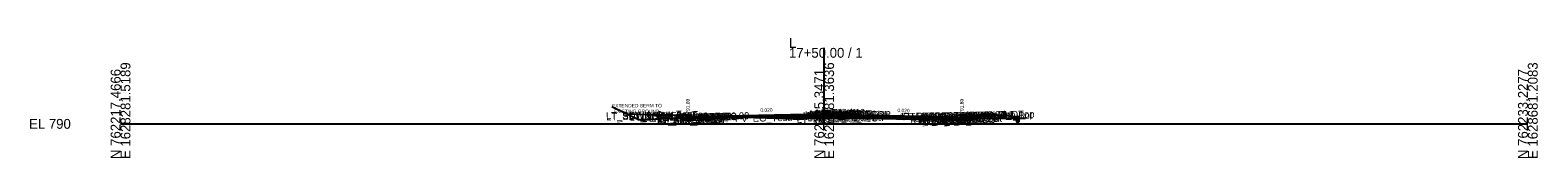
# Model space of a CAD drawing. Extents: x -26 to 4403, y -510 to 9556.
# Drawn here: x -25.7 to 402.8, y 7490.3 to 7524.4 of the extents above; entities that cross this region are included whole.
import ezdxf

# ---------------------------------------------------------------- set-up
doc = ezdxf.new("R2010")
doc.units = 0
for name, color, linetype in [('Default', 7, 'Continuous'), ('Exist CMT Pavement', 7, 'Continuous'), ('Exist Cross Section Cell', 7, 'Continuous'), ('Exist XS Ground Line', 7, 'Continuous'), ('Exist XS Void Line', 7, 'Continuous'), ('Prop CMT Conc Surface', 7, 'Continuous'), ('Prop CMT Concrete Structures', 7, 'Continuous'), ('Prop CMT Pvmt Course 1', 7, 'Continuous'), ('Prop CMT Pvmt Course 1 CG', 7, 'Continuous'), ('Prop CMT Pvmt Course 1 Wedge', 7, 'Continuous'), ('Prop CMT Pvmt Course 2', 7, 'Continuous'), ('Prop CMT Pvmt Course 2 Wedge', 7, 'Continuous'), ('Prop CMT Pvmt Course 3', 7, 'Continuous'), ('Prop CMT Pvmt Course 3 Wedge', 7, 'Continuous'), ('Prop CMT Pvmt Surface', 7, 'Continuous'), ('Prop CMT Pvmt Wedge Surface 1', 7, 'Continuous'), ('Prop CMT Pvmt Wedge Surface 2', 7, 'Continuous'), ('Prop CMT Pvmt Wedge Surface 3', 7, 'Continuous'), ('Prop CMT Slope Grass', 7, 'Continuous'), ('Prop CMT Subgrade Earthwork', 7, 'Continuous'), ('Prop XS Finish Grade CurbGutter', 7, 'Continuous'), ('Prop XS Hydro Elevations', 7, 'Continuous'), ('Prop XS SE Text', 7, 'Continuous'), ('Prop XS Side Slope Text', 7, 'Continuous'), ('Scratch_Level_0', 7, 'Continuous')]:
    doc.layers.add(name, color=color, linetype=linetype)

msp = doc.modelspace()

# ---------------------------------------------------------------- linework, layer by layer
at = {"layer": 'Exist CMT Pavement'}
for points in [[(163.26, 7501.84), (170.58, 7501.94), (180.37, 7501.79), (180.75, 7501.78), (181.13, 7501.77), (191.19, 7501.47)], [(191.19, 7501.47), (191.34, 7501.46)]]:
    msp.add_lwpolyline(points, dxfattribs=at)
at = {"layer": 'Exist Cross Section Cell'}
for p, q in [((200, 7500), (200, 7521.59)), ((0, 7500), (200, 7500)), ((200, 7500), (400, 7500))]:
    msp.add_line(p, q, dxfattribs=at)
at = {"layer": 'Exist XS Ground Line'}
for p, q in [((139.65, 7504.97), (147.23, 7501.25)), ((147.23, 7501.25), (149.96, 7501.25))]:
    msp.add_line(p, q, dxfattribs=at)
msp.add_lwpolyline([(149.96, 7501.25), (150.33, 7501.27), (160.36, 7501.79), (170.58, 7501.94), (180.37, 7501.79), (180.75, 7501.78), (181.13, 7501.77), (191.19, 7501.47), (193.08, 7501.34), (196.33, 7501.62)], dxfattribs=at)
at = {"layer": 'Exist XS Void Line'}
msp.add_line((196.33, 7501.62), (257.17, 7501.62), dxfattribs=at)
at = {"layer": 'Prop CMT Conc Surface'}
for points in [[(156.75, 7502.48), (151.75, 7502.58)], [(161.25, 7501.9), (161.25, 7502.4), (160.75, 7502.4)], [(163.25, 7502.02), (161.25, 7501.9)], [(237.1, 7502.01), (239.1, 7501.89)], [(239.1, 7501.89), (239.1, 7502.39), (239.6, 7502.39)], [(243.61, 7502.48), (248.61, 7502.58)]]:
    msp.add_lwpolyline(points, dxfattribs=at)
at = {"layer": 'Prop CMT Concrete Structures'}
for points in [[(151.75, 7502.25), (151.75, 7502.58)], [(151.75, 7502.58), (156.75, 7502.48)], [(156.75, 7502.15), (151.75, 7502.25)], [(156.75, 7502.48), (156.75, 7502.15)], [(163.25, 7502.02), (161.25, 7501.9), (161.25, 7502.4), (160.75, 7502.4)], [(160.75, 7502.4), (160.75, 7501.38), (163.25, 7501.43)], [(163.25, 7501.43), (163.25, 7502.02)], [(208, 7502.59), (207.99, 7502.76), (207.24, 7503.01), (206, 7503.27), (204.76, 7503.25), (204.01, 7503), (204, 7502.83)], [(204, 7502.83), (208, 7502.59)], [(237.1, 7502.01), (239.1, 7501.89), (239.1, 7502.39), (239.6, 7502.39)], [(239.6, 7502.39), (239.6, 7501.38), (237.1, 7501.42)], [(237.1, 7501.42), (237.1, 7502.01)], [(248.61, 7502.58), (243.61, 7502.48)], [(243.61, 7502.48), (243.61, 7502.14)], [(243.61, 7502.14), (248.61, 7502.24)], [(248.61, 7502.24), (248.61, 7502.58)]]:
    msp.add_lwpolyline(points, dxfattribs=at)
at = {"layer": 'Prop CMT Pvmt Course 1'}
for points in [[(204, 7502.83), (163.25, 7502.02)], [(163.25, 7501.89), (204, 7502.7)], [(163.25, 7502.02), (163.25, 7501.77), (163.25, 7501.77), (163.25, 7501.89)], [(204, 7502.83), (208, 7502.59)], [(204, 7502.58), (204, 7502.83)], [(204, 7502.58), (204, 7502.83)], [(204, 7502.7), (204, 7502.58), (204, 7502.58)], [(208, 7502.34), (204, 7502.58)], [(208, 7502.59), (208, 7502.34)], [(208, 7502.59), (237.1, 7502.01)], [(208, 7502.34), (208, 7502.59)], [(237.1, 7501.76), (208, 7502.34)], [(237.1, 7502.01), (237.1, 7501.76)]]:
    msp.add_lwpolyline(points, dxfattribs=at)
msp.add_lwpolyline([(208, 7502.34), (208, 7502.47), (208, 7502.47), (208, 7502.34)], close=True, dxfattribs=at)
at = {"layer": 'Prop CMT Pvmt Course 1 CG'}
for points in [[(163.25, 7501.43), (160.25, 7501.37), (159.91, 7501.03)], [(159.91, 7501.03), (163.25, 7501.1)], [(237.1, 7501.42), (240.1, 7501.37), (240.44, 7501.03)], [(237.1, 7501.09), (237.1, 7501.42)], [(240.44, 7501.03), (237.1, 7501.09)]]:
    msp.add_lwpolyline(points, dxfattribs=at)
at = {"layer": 'Prop CMT Pvmt Course 1 Wedge'}
for points in [[(163.25, 7501.89), (170.58, 7502.04), (180.37, 7502.23), (180.75, 7502.24), (181.13, 7502.25), (191.19, 7502.45), (193.05, 7502.49), (193.08, 7502.49), (193.09, 7502.49), (193.1, 7502.49), (193.14, 7502.49), (196.33, 7502.55), (204, 7502.7)], [(204, 7502.58), (196.33, 7502.43), (193.14, 7502.36), (193.1, 7502.36), (193.09, 7502.36), (193.08, 7502.36), (193.05, 7502.36), (191.19, 7502.32), (181.13, 7502.12), (180.75, 7502.11), (180.37, 7502.11), (171.32, 7501.93), (170.58, 7501.94), (163.25, 7501.83)], [(163.25, 7501.83), (163.25, 7501.89)], [(204, 7502.7), (204, 7502.58)]]:
    msp.add_lwpolyline(points, dxfattribs=at)
at = {"layer": 'Prop CMT Pvmt Course 2'}
for points in [[(163.25, 7501.43), (163.25, 7501.43), (163.25, 7501.77), (163.25, 7501.77)], [(163.25, 7501.77), (163.25, 7501.43)], [(204, 7502.58), (208, 7502.34)], [(204, 7502.25), (204, 7502.58)], [(208, 7502.01), (204, 7502.25)], [(208, 7502.34), (208, 7502.01)], [(208, 7502.01), (208, 7502.34)], [(208, 7502.34), (237.1, 7501.76)], [(237.1, 7501.42), (208, 7502.01)], [(237.1, 7501.76), (237.1, 7501.42)]]:
    msp.add_lwpolyline(points, dxfattribs=at)
at = {"layer": 'Prop CMT Pvmt Course 2 Wedge'}
for points in [[(204, 7502.25), (196.33, 7502.09), (193.14, 7502.03), (193.1, 7502.03), (193.09, 7502.03), (193.08, 7502.03), (193.05, 7502.03), (191.19, 7501.99), (181.13, 7501.79), (180.75, 7501.78), (180.7, 7501.78), (180.37, 7501.79), (171.32, 7501.93)], [(171.32, 7501.93), (180.37, 7502.11)], [(180.37, 7502.11), (180.75, 7502.11), (181.13, 7502.12), (191.19, 7502.32), (193.05, 7502.36), (193.08, 7502.36), (193.09, 7502.36), (193.1, 7502.36), (193.14, 7502.36), (196.33, 7502.43), (204, 7502.58)], [(204, 7502.58), (204, 7502.25)]]:
    msp.add_lwpolyline(points, dxfattribs=at)
at = {"layer": 'Prop CMT Pvmt Course 3'}
for points in [[(163.25, 7501.43), (163.25, 7501.43), (163.25, 7501.1), (163.25, 7501.1)], [(163.25, 7501.1), (163.25, 7501.43)], [(204, 7502.25), (208, 7502.01)], [(204, 7501.91), (204, 7502.25)], [(208, 7501.67), (204, 7501.91)], [(208, 7502.01), (208, 7501.67)], [(208, 7502.01), (237.1, 7501.42)], [(208, 7501.67), (208, 7502.01)], [(237.1, 7501.09), (208, 7501.67)], [(237.1, 7501.42), (237.1, 7501.09)]]:
    msp.add_lwpolyline(points, dxfattribs=at)
at = {"layer": 'Prop CMT Pvmt Course 3 Wedge'}
for points in [[(204, 7501.71), (196.33, 7501.62), (193.14, 7501.34), (193.1, 7501.34), (193.09, 7501.34), (193.08, 7501.34), (193.05, 7501.34), (191.19, 7501.47), (181.13, 7501.77), (180.75, 7501.78), (180.69, 7501.78)], [(180.69, 7501.78), (180.75, 7501.78)], [(180.75, 7501.78), (181.13, 7501.79), (191.19, 7501.99), (193.05, 7502.03), (193.08, 7502.03), (193.09, 7502.03), (193.1, 7502.03), (193.14, 7502.03), (196.33, 7502.09), (204, 7502.25)], [(204, 7502.25), (204, 7501.71)]]:
    msp.add_lwpolyline(points, dxfattribs=at)
at = {"layer": 'Prop CMT Pvmt Surface'}
for points in [[(204, 7502.83), (163.25, 7502.02)], [(204, 7502.83), (208, 7502.59)], [(208, 7502.59), (237.1, 7502.01)]]:
    msp.add_lwpolyline(points, dxfattribs=at)
at = {"layer": 'Prop CMT Pvmt Wedge Surface 1'}
for points in [[(204, 7502.7), (163.25, 7501.89)], [(163.25, 7501.77), (163.25, 7502.02)], [(163.25, 7501.89), (163.25, 7501.77), (163.25, 7501.77)], [(204, 7502.83), (204, 7502.58), (204, 7502.58), (204, 7502.7)]]:
    msp.add_lwpolyline(points, dxfattribs=at)
at = {"layer": 'Prop CMT Pvmt Wedge Surface 2'}
for points in [[(204, 7502.58), (163.25, 7501.77)], [(163.25, 7501.77), (163.25, 7502.02)], [(204, 7502.83), (204, 7502.58)]]:
    msp.add_lwpolyline(points, dxfattribs=at)
at = {"layer": 'Prop CMT Pvmt Wedge Surface 3'}
for points in [[(204, 7502.25), (163.25, 7501.43)], [(163.25, 7501.43), (163.25, 7502.02)], [(204, 7502.83), (204, 7502.25)]]:
    msp.add_lwpolyline(points, dxfattribs=at)
at = {"layer": 'Prop CMT Slope Grass'}
for p, q in [((248.61, 7502.57), (249.1, 7502.58)), ((249.1, 7502.58), (254.68, 7502.12))]:
    msp.add_line(p, q, dxfattribs=at)
for points in [[(151.25, 7502.58), (144.21, 7502.73)], [(160.75, 7502.4), (151.25, 7502.58)], [(239.6, 7502.39), (248.61, 7502.57)], [(254.68, 7502.12), (254.68, 7500.62), (255.35, 7500.62), (255.35, 7501.62)]]:
    msp.add_lwpolyline(points, dxfattribs=at)
at = {"layer": 'Prop CMT Subgrade Earthwork'}
msp.add_line((191.34, 7501.46), (191.34, 7501.66), dxfattribs=at)
for points in [[(163.25, 7501.1), (159.91, 7501.03), (158.5, 7502.44)], [(163.25, 7501.1), (163.26, 7501.83)], [(163.25, 7501.1), (163.25, 7501.1)], [(204, 7501.91), (191.34, 7501.66)], [(204, 7501.91), (208, 7501.67)], [(208, 7501.67), (237.1, 7501.09)], [(237.1, 7501.09), (240.44, 7501.03), (241.84, 7502.43)]]:
    msp.add_lwpolyline(points, dxfattribs=at)
at = {"layer": 'Prop XS Finish Grade CurbGutter'}
for p, q in [((254.68, 7502.12), (254.87, 7502.12)), ((254.68, 7502.12), (255.35, 7502.12)), ((254.68, 7502.12), (254.68, 7501.12)), ((254.68, 7501.12), (254.68, 7500.62)), ((254.68, 7501.12), (255.35, 7501.12)), ((254.68, 7500.62), (255.35, 7500.62)), ((255.35, 7501.7), (254.99, 7502.07)), ((255.35, 7501.7), (255.35, 7501.12)), ((255.35, 7501.62), (255.35, 7501.62)), ((255.35, 7501.12), (255.35, 7500.62))]:
    msp.add_line(p, q, dxfattribs=at)
msp.add_arc((254.87, 7501.95), 0.166, 43.9997, 90, dxfattribs=at)

# ---------------------------------------------------------------- texts
at = {"layer": 'Default'}
msp.add_text('-', height=0.0001, dxfattribs=at).set_placement((0, 7500))
at = {"layer": 'Exist Cross Section Cell'}
for s, p in [('17+50.00 / 1', (190, 7518.79)), ('L', (190, 7521.59)), ('EL 790', (-26, 7498.6))]:
    msp.add_text(s, height=2.8, dxfattribs=at).set_placement(p)
for s, p in [('E 1628281.5189', (2.8, 7490)), ('E 1628481.3636', (202.8, 7490)), ('E 1628681.2083', (402.8, 7490)), ('N 762217.4666', (0, 7490)), ('N 762225.3471', (200, 7490)), ('N 762233.2277', (400, 7490))]:
    msp.add_text(s, height=2.8, rotation=90, dxfattribs=at).set_placement(p)
at = {"layer": 'Prop XS Hydro Elevations'}
for p in [(161.75, 7502.9), (239.6, 7502.89)]:
    msp.add_text('791.89', height=1, rotation=90, dxfattribs=at).set_placement(p)
at = {"layer": 'Prop XS SE Text'}
for rotation, p in [(1.1458, (181.86, 7503.39)), (358.8541, (220.82, 7503.33))]:
    msp.add_text('0.020', height=1, rotation=rotation, dxfattribs=at).set_placement(p)
at = {"layer": 'Prop XS Side Slope Text'}
for s, p in [('EXTENDED BERM TO', (139.68, 7504.69)), ('EXISTING GROUND', (140.19, 7503.06))]:
    msp.add_text(s, height=1, dxfattribs=at).set_placement(p)
msp.add_text('VAR.', height=1, rotation=355.293, dxfattribs=at).set_placement((250.28, 7502.57))
at = {"layer": 'Scratch_Level_0'}
for s, p in [('LT_SDWK_Out_Top', (138.01, 7501.31)), ('LT_SDWK_In_Top', (144.63, 7501.24)), ('LT_PV2_IEEOP', (193.97, 7501.38)), ('LT_PV1_IEEOP', (194.54, 7501.52)), ('LT_PV2_PGL1', (194.9, 7501.4)), ('LT_PV2_PGL', (195.23, 7501.4)), ('LT_PV1_PGL', (195.8, 7501.67)), ('MI_Face In', (195.92, 7501.83)), ('MI_Top In', (197.63, 7502.1)), ('RT_PV1_OEEOP', (197.85, 7501.26)), ('17+50.00', (197.84, 7501.82)), ('17+50.00', (198.07, 7501.95)), ('MI_Face Out', (198.28, 7501.56)), ('MI_Top Out', (198.49, 7501.83)), ('RT_PV1_IEEOP', (198.49, 7501.27)), ('MI_Crown', (199.09, 7502.13)), ('MI_Bot Out', (199.28, 7501.42)), ('RT_PV1_PGL', (199.75, 7501.42)), ('17+50.00', (200.47, 7502.01)), ('17+50.00', (201.75, 7501.66)), ('17+50.00', (201.82, 7501.61)), ('RT_Sub_Trench_Out_DLT', (222.39, 7501.04)), ('RT_CG_Top_BOC', (227.86, 7501.15)), ('RT_SDWK_In_Top', (231.44, 7501.23)), ('RT_SDWK_Out_Top', (234.82, 7501.3)), ('RT_Shld_O', (241.17, 7501.42)), ('LT_SDWK_Out_Bot', (138.04, 7500.98)), ('LT_SDWK_In_Bot', (144.66, 7500.91)), ('LT_PV_Sub_Tie_Out', (148.23, 7500.53)), ('LT_PV_OEEOP_EG', (150.82, 7500.59)), ('17+50.00', (152.1, 7501.25)), ('LT_Sub_OEEOP', (152.48, 7499.88)), ('LT_PV2_OEEOP', (152.58, 7500.55)), ('LT_PV3_OEEOP', (152.58, 7500.22)), ('LT_PV1_OEEOP', (153.15, 7500.69)), ('LT_Sub_OEOT', (153.35, 7499.9)), ('LT_PV2_OEOT', (153.45, 7500.57)), ('LT_PV3_OEOT', (153.45, 7500.24)), ('LT_PV1_OEOT', (154.01, 7500.83)), ('17+50.00', (167.51, 7501.1)), ('LT_PV_EG_TestPt', (170.06, 7500.42)), ('LT_PV_IEEOP_EG', (192.21, 7500.24)), ('LT_PV3_IEEOP', (193.97, 7501.05)), ('LT_PV3_PGL1', (194.9, 7501.06)), ('LT_PV3_PGL', (195.23, 7501.07)), ('LT_PV4_PGL', (195.23, 7500.74)), ('RT_Sub_OEEOP', (197.19, 7500.46)), ('RT_PV2_OEEOP', (197.28, 7501.13)), ('RT_PV3_OEEOP', (197.28, 7500.79)), ('RT_PV2_IEEOP', (197.93, 7501.14)), ('RT_PV2_PGL1', (198.86, 7501.16)), ('RT_PV3_PGL1', (198.86, 7500.82)), ('RT_PV2_PGL', (199.19, 7501.16)), ('RT_PV4_PGL', (199.19, 7500.5)), ('17+50.00', (221.51, 7501.07)), ('RT_Sub_OEOT_CG', (224.44, 7499.84)), ('RT_CG_Top_Face', (226.33, 7501.13)), ('RT_CG1_Shelf_Out', (226.62, 7500.1)), ('RT_CG_Bot_IE', (226.98, 7500.22)), ('RT_Sub_OEOT', (227.15, 7499.89)), ('RT_PV2_OEOT', (227.24, 7500.56)), ('RT_PV3_OEOT', (227.24, 7500.23)), ('RT_CG_Top_Gut', (227.31, 7500.65)), ('RT_PV1_OEOT', (227.81, 7500.82)), ('RT_CG_Bot_BOC', (227.89, 7500.14)), ('RT_Sub_OEOP', (230.52, 7499.83)), ('RT_SDWK_In_Bot', (231.48, 7500.9)), ('17+50.00', (233.17, 7501.26)), ('RT_SDWK_Out_Bot', (234.85, 7500.97)), ('17+50.00', (235.38, 7501.3))]:
    msp.add_text(s, height=2, rotation=1.1458, dxfattribs=at).set_placement(p)

doc.saveas('drawing.dxf')
